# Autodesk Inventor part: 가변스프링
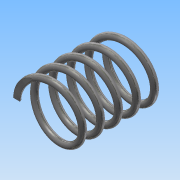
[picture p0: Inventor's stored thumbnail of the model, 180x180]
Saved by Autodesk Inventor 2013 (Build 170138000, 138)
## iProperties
Created: 2017-12
Part Number: 가변스프링
Material: 스테인리스강
Document SubType Name: Modeling
Designer: Administrator
Density: 1 g/cm^3
Mass: 0.875036 g
Surface Area: 17.7388 cm^2
Volume: 0.875036 cm^3
Author: Administrator
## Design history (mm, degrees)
sketch "스케치1"
  geometry: L1 (0, 0)-(-9, 0); L2 (-9, 0)-(-9, 28.5); L3 (-9, 28.5)-(0, 28.5); L4 (0, 28.5)-(0, 0); C1 r 1 at (-9, 0)
  constraints: 8 end point, 2 parallel, 1 centre point, 1 coincident, 1 horizontal, 1 perpendicular
  dimensions: "d1" = 28.5 distance of L1.end L2.end (derived); "d2" = 2 diameter of C1; "d13" = 18 diameter of L2 L4
feature "코일1" sketch "스케치1" pitch "d3" = 10; turns "d5" = 5; dims "d4" = 28.5 (= d1), "d6" = 0, angle "d7" = 90 deg, angle "d8" = 90 deg, "d9" = 0, "d10" = 0
sketch "스케치2"
  geometry: L1 (0, -26.74)-(28.5, -26.74); L2 (28.5, -26.74)-(28.5, 27.085); L3 (28.5, 27.085)-(0, 27.085); L4 (0, 27.085)-(0, -26.74); 4 further points
  constraints: 8 end point, 2 midpoint, 2 parallel, 2 vertical alignment, 1 horizontal, 1 perpendicular
extrude "돌출1" sketch "스케치2" stored distance "d11" = 0; taper "d12" = 0 deg
node "솔리드1"
